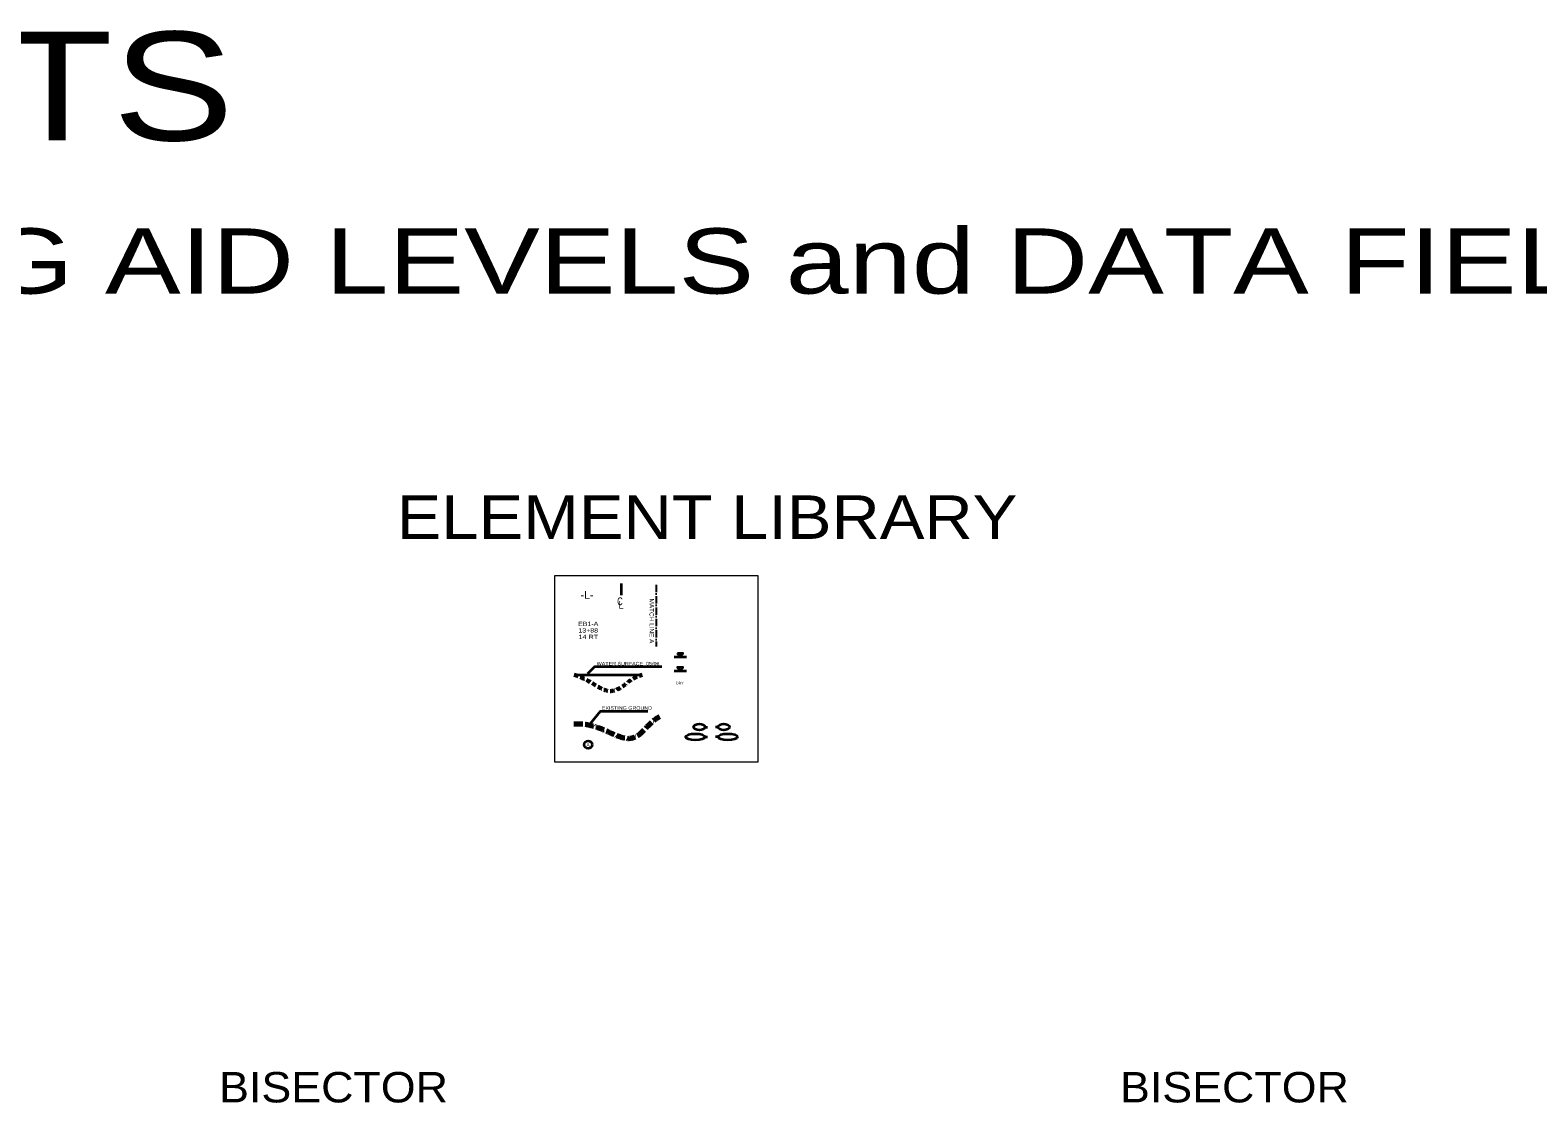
# Model space of a CAD drawing. Extents: x 278712 to 279914, y 171254 to 171792.
# Drawn here: x 279269.8 to 279616.6, y 171536.1 to 171782.9 of the extents above; entities that cross this region are included whole.
import ezdxf
from ezdxf.enums import TextEntityAlignment as Align

# ---------------------------------------------------------------- set-up
doc = ezdxf.new("R2010")
doc.units = 0
doc.header["$LTSCALE"] = 0.34
for name, pattern in [('DOT_DASHED', [7.7, 5, -1.2, 0.3, -1.2]), ('LONG_DASHED', [7.5, 6, -1.5]), ('MEDIUM_DASHED', [4.5, 3, -1.5])]:
    doc.linetypes.add(name, pattern=pattern)
for name, color, linetype in [('15', 7, 'Continuous'), ('24', 7, 'Continuous'), ('49', 7, 'Continuous'), ('61', 7, 'Continuous')]:
    doc.layers.add(name, color=color, linetype=linetype)
for name, color, linetype, lineweight in [('21', 7, 'Continuous', 35), ('22', 7, 'Continuous', 35), ('23', 7, 'Continuous', 35), ('25', 7, 'Continuous', 35), ('29', 7, 'Continuous', 35), ('30', 7, 'MEDIUM_DASHED', 60), ('31', 7, 'Continuous', 35), ('41', 7, 'Continuous', 35), ('48', 7, 'Continuous', 13), ('56', 7, 'DOT_DASHED', 25), ('62', 7, 'Continuous', 35)]:
    doc.layers.add(name, color=color, linetype=linetype, lineweight=lineweight)

msp = doc.modelspace()

# ---------------------------------------------------------------- hatches: boundary and pattern name
at = {"layer": '22'}
msp.add_hatch(color=256, dxfattribs=at).paths.add_polyline_path([(279418.7389, 171639.552), (279419.9484, 171639.552), (279419.3436, 171638.687)])

# ---------------------------------------------------------------- linework, layer by layer
at = {"layer": '21'}
for p, q in [((279417.9374, 171635.464), (279419.3436, 171635.464)), ((279419.3436, 171635.464), (279420.7499, 171635.464))]:
    msp.add_line(p, q, dxfattribs=at)
msp.add_lwpolyline([(279419.3436, 171635.464), (279418.7389, 171636.3287), (279419.9484, 171636.3287)], close=True, dxfattribs=at)
at = {"layer": '22'}
for p, q in [((279417.9374, 171638.687), (279419.3436, 171638.687)), ((279419.3436, 171638.687), (279420.7499, 171638.687))]:
    msp.add_line(p, q, dxfattribs=at)
msp.add_lwpolyline([(279418.7389, 171639.552), (279419.9484, 171639.552), (279419.3436, 171638.687)], close=True, dxfattribs=at)
at = {"layer": '22', "linetype": 'LONG_DASHED', "lineweight": 70}
msp.add_open_spline([(279394.8956, 171623.3112), (279396.0044, 171623.4007), (279399.0011, 171623.1417), (279402.6311, 171621.561), (279407.2274, 171619.4065), (279410.3841, 171620.722), (279413.0496, 171624.281), (279414.6699, 171624.9847)], degree=3, dxfattribs=at)
at = {"layer": '23'}
msp.add_lwpolyline([(279411.8764, 171626.1337), (279400.9084, 171626.1337), (279398.5581, 171623.224)], dxfattribs=at)
at = {"layer": '25'}
for p, q in [((279425.0434, 171622.5727), (279425.6059, 171622.5727)), ((279428.0286, 171622.5727), (279427.4661, 171622.5727)), ((279425.0434, 171620.2887), (279425.6059, 171620.2887)), ((279428.0286, 171620.2887), (279427.4661, 171620.2887))]:
    msp.add_line(p, q, dxfattribs=at)
for centre, major_axis, ratio in [((279422.812, 171620.2888), (2.2313, 0), 0.332773), ((279423.7308, 171622.5727), (1.3125, 0), 0.565714), ((279429.3412, 171622.5727), (1.3125, 0), 0.565714), ((279430.26, 171620.2888), (2.2313, 0), 0.332773)]:
    msp.add_ellipse(centre, major_axis=major_axis, ratio=ratio, dxfattribs=at)
at = {"layer": '29'}
msp.add_line((279394.9199, 171634.5812), (279410.5644, 171634.5812), dxfattribs=at)
at = {"layer": '30'}
msp.add_open_spline([(279394.9199, 171634.5812), (279397.8966, 171633.5715), (279400.5544, 171631.4982), (279403.5841, 171630.382), (279406.7034, 171632.143), (279408.1694, 171633.763), (279410.5644, 171634.5812)], degree=3, dxfattribs=at)
at = {"layer": '31'}
msp.add_lwpolyline([(279415.1189, 171636.3887), (279399.5974, 171636.3887), (279398.0029, 171634.794)], dxfattribs=at)
at = {"layer": '41'}
msp.add_circle((279398.1558, 171618.5062), 0.9, dxfattribs=at)
at = {"layer": '48'}
msp.add_lwpolyline([(279390.4639, 171657.4362), (279437.1439, 171657.4362), (279437.1439, 171614.4955), (279390.4639, 171614.4955)], close=True, dxfattribs=at)
at = {"layer": '56'}
msp.add_line((279413.7996, 171655.307), (279413.7996, 171641.1145), dxfattribs=at)
at = {"layer": '62'}
msp.add_line((279405.7211, 171655.552), (279405.7211, 171652.9397), dxfattribs=at)

# ---------------------------------------------------------------- texts
at = {"layer": '15', "width": 1.05}
msp.add_text('-L-', height=1.75, dxfattribs=at).set_placement((279397.8946, 171652.0947), align=Align.CENTER)
at = {"layer": '23', "width": 1.15}
msp.add_text('EXISTING GROUND', height=0.8, dxfattribs=at).set_placement((279401.3019, 171626.559))
at = {"layer": '24'}
msp.add_text('DRY', height=0.5859, dxfattribs=at).set_placement((279419.2306, 171632.38), align=Align.CENTER)
at = {"layer": '31', "width": 1.15}
msp.add_text('WATER SURFACE  05/06', height=0.8, dxfattribs=at).set_placement((279400.1291, 171636.758))
at = {"layer": '41', "width": 0.75}
msp.add_text('A', height=0.8, dxfattribs=at).set_placement((279398.1371, 171618.1062), align=Align.CENTER)
at = {"layer": '49'}
for s, width, p in [('EB1-A', 1.2, (279398.1795, 171645.7995)), ('13+88', 1.2, (279398.1704, 171644.2995)), ('14 RT', 1.25, (279398.202, 171642.7995))]:
    msp.add_text(s, height=1, dxfattribs=dict(at, width=width)).set_placement(p, align=Align.CENTER)
at = {"layer": '56', "width": 1.1}
msp.add_text('MATCH LINE A', height=1, rotation=270, dxfattribs=at).set_placement((279412.2681, 171652.1177))
at = {"layer": '61'}
for s, height, width, p in [('ENGLISH UNITS', 25, 1.25, (278996.2619, 171757.5135)), ('(TURN OFF DRAFTING AID LEVELS and DATA FIELDS FOR FINAL PLOTS)', 15, 1.3, (278998.7991, 171722.2772))]:
    msp.add_text(s, height=height, dxfattribs=dict(at, width=width)).set_placement(p)
at = {"layer": '62'}
for s, height, width, p in [('ELEMENT LIBRARY', 10, 1.15, (279354.1384, 171665.8527)), ('C', 1.8, 0.7, (279404.8406, 171650.593)), ('L', 1.8, 0.9, (279405.1196, 171649.7665)), ('BISECTOR', 7, 1.1, (279313.2864, 171536.2072)), ('BISECTOR', 7, 1.1, (279520.4691, 171536.2072))]:
    msp.add_text(s, height=height, dxfattribs=dict(at, width=width)).set_placement(p)

doc.saveas('drawing.dxf')
